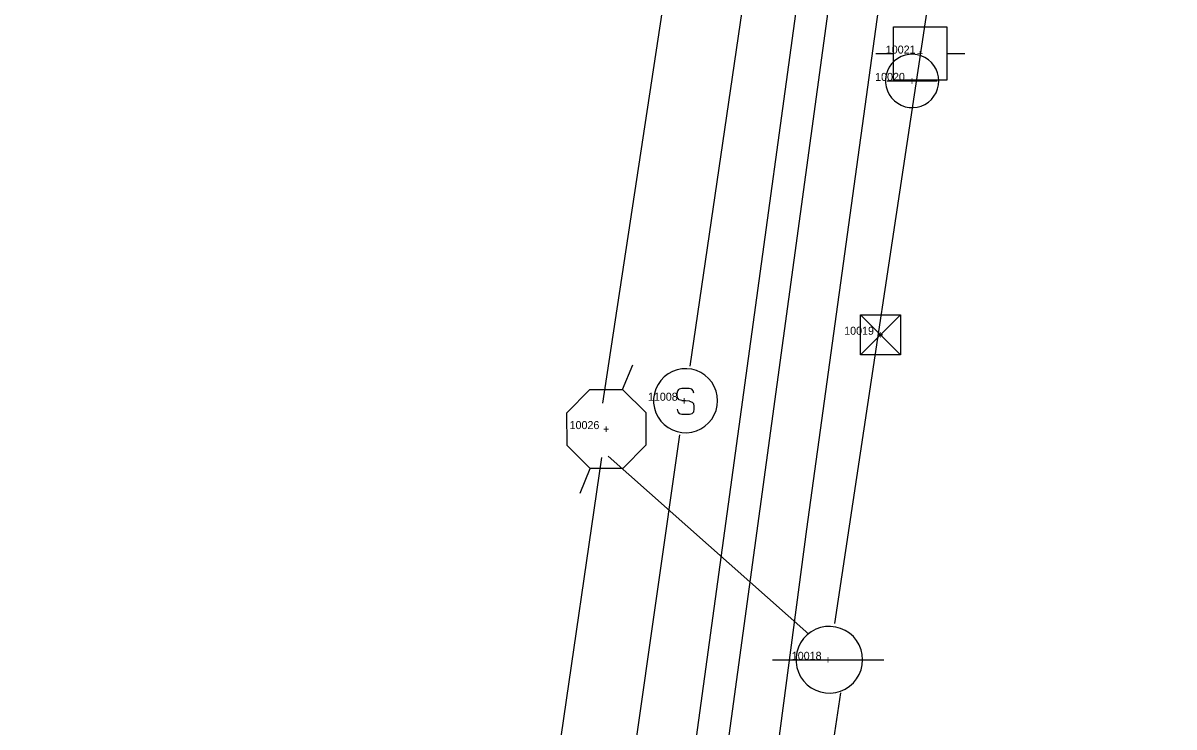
# Model space of a CAD drawing. Extents: x 1795905 to 1799611, y 243768 to 252016.
# Drawn here: x 1797411.2 to 1797626.9, y 244846.2 to 244978 of the extents above; entities that cross this region are included whole.
import ezdxf

# ---------------------------------------------------------------- set-up
doc = ezdxf.new("R2010")
doc.units = 0
for name, color, linetype in [('Level 50', 7, 'Continuous'), ('LS-SURVEY POINT', 7, 'Continuous'), ('OHUT', 7, 'Continuous'), ('OHUTTXT', 7, 'Continuous'), ('UGUT', 7, 'Continuous'), ('UGUTTXT', 7, 'Continuous')]:
    doc.layers.add(name, color=color, linetype=linetype)

msp = doc.modelspace()

# ---------------------------------------------------------------- linework, layer by layer
at = {"layer": 'Level 50'}
for p, q in [((1797523.61, 244909.35), (1797525.51, 244913.98)), ((1797515.63, 244889.93), (1797517.53, 244894.55))]:
    msp.add_line(p, q, dxfattribs=at)
msp.add_lwpolyline([(1797523.65, 244894.57), (1797517.53, 244894.55), (1797513.19, 244898.87), (1797513.17, 244904.99), (1797517.49, 244909.34), (1797523.61, 244909.35), (1797527.95, 244905.03), (1797527.97, 244898.91)], close=True, dxfattribs=at)
at = {"layer": 'OHUT'}
for p, q in [((1797574.38, 244977.28), (1797584.38, 244977.28)), ((1797574.38, 244967.28), (1797574.38, 244977.28)), ((1797584.38, 244977.28), (1797584.38, 244967.28)), ((1797571.05, 244972.28), (1797574.38, 244972.28)), ((1797584.38, 244972.28), (1797587.71, 244972.28)), ((1797584.38, 244967.28), (1797574.38, 244967.28)), ((1797551.72, 244858.74), (1797572.55, 244858.74))]:
    msp.add_line(p, q, dxfattribs=at)
msp.add_lwpolyline([(1797568.59, 244858.74), (1797568.52, 244859.7), (1797568.3, 244860.63), (1797567.95, 244861.52), (1797567.46, 244862.34), (1797566.85, 244863.08), (1797566.14, 244863.71), (1797565.33, 244864.24), (1797564.46, 244864.63), (1797563.54, 244864.88), (1797562.58, 244864.99), (1797561.63, 244864.95), (1797560.69, 244864.77), (1797559.79, 244864.45), (1797558.95, 244863.99), (1797558.19, 244863.41), (1797557.52, 244862.72), (1797556.97, 244861.94), (1797556.55, 244861.08), (1797556.26, 244860.17), (1797556.11, 244859.22), (1797556.11, 244858.27), (1797556.26, 244857.32), (1797556.55, 244856.41), (1797556.97, 244855.55), (1797557.52, 244854.77), (1797558.19, 244854.08), (1797558.95, 244853.5), (1797559.79, 244853.04), (1797560.69, 244852.72), (1797561.63, 244852.54), (1797562.58, 244852.5), (1797563.54, 244852.61), (1797564.46, 244852.86), (1797565.33, 244853.25), (1797566.14, 244853.77), (1797566.85, 244854.41), (1797567.46, 244855.15), (1797567.95, 244855.97), (1797568.3, 244856.86), (1797568.52, 244857.79)], close=True, dxfattribs=at)
at = {"layer": 'OHUTTXT'}
for p, q in [((1797563.38, 244865.55), (1797623.41, 245263.36)), ((1797519.91, 244906.82), (1797537.24, 245021.05)), ((1797505.88, 244801.76), (1797519.74, 244896.6)), ((1797520.91, 244896.85), (1797558.53, 244863.55)), ((1797542.26, 244706.1), (1797564.52, 244852.58))]:
    msp.add_line(p, q, dxfattribs=at)
at = {"layer": 'UGUT'}
for p, q in [((1797573.21, 244967.17), (1797582.54, 244967.17)), ((1797568.21, 244923.37), (1797575.71, 244915.87)), ((1797575.71, 244923.37), (1797568.21, 244915.87)), ((1797533.81, 244908.22), (1797533.81, 244908.67)), ((1797533.94, 244907.77), (1797533.81, 244908.22)), ((1797536.56, 244909.43), (1797536.05, 244909.56)), ((1797536.82, 244909.11), (1797536.56, 244909.43)), ((1797536.95, 244908.67), (1797536.82, 244909.11)), ((1797534.2, 244907.45), (1797533.94, 244907.77)), ((1797534.71, 244907.32), (1797534.2, 244907.45)), ((1797536.12, 244907.19), (1797534.71, 244907.32)), ((1797536.12, 244907.19), (1797536.63, 244907)), ((1797536.95, 244906.68), (1797536.63, 244907)), ((1797537.01, 244906.23), (1797536.95, 244906.68)), ((1797537.01, 244905.66), (1797537.01, 244906.23)), ((1797533.81, 244905.66), (1797533.94, 244905.21)), ((1797533.94, 244905.21), (1797534.2, 244904.89)), ((1797534.2, 244904.89), (1797534.71, 244904.76)), ((1797534.71, 244904.76), (1797536.12, 244904.76)), ((1797536.12, 244904.76), (1797536.63, 244904.89)), ((1797536.63, 244904.89), (1797536.95, 244905.21)), ((1797536.95, 244905.21), (1797537.01, 244905.66))]:
    msp.add_line(p, q, dxfattribs=at)
for points in [[(1797582.87, 244967.17), (1797582.82, 244967.93), (1797582.64, 244968.67), (1797582.36, 244969.38), (1797581.96, 244970.04), (1797581.48, 244970.63), (1797580.91, 244971.14), (1797580.26, 244971.56), (1797579.56, 244971.87), (1797578.83, 244972.07), (1797578.07, 244972.16), (1797577.3, 244972.13), (1797576.55, 244971.99), (1797575.83, 244971.73), (1797575.16, 244971.36), (1797574.55, 244970.9), (1797574.02, 244970.35), (1797573.58, 244969.72), (1797573.24, 244969.03), (1797573.01, 244968.3), (1797572.89, 244967.55), (1797572.89, 244966.78), (1797573.01, 244966.03), (1797573.24, 244965.3), (1797573.58, 244964.61), (1797574.02, 244963.98), (1797574.55, 244963.43), (1797575.16, 244962.97), (1797575.83, 244962.6), (1797576.55, 244962.34), (1797577.3, 244962.2), (1797578.07, 244962.17), (1797578.83, 244962.26), (1797579.56, 244962.46), (1797580.26, 244962.77), (1797580.91, 244963.19), (1797581.48, 244963.7), (1797581.96, 244964.29), (1797582.36, 244964.95), (1797582.64, 244965.66), (1797582.82, 244966.4)], [(1797568.21, 244923.37), (1797575.71, 244923.37), (1797575.71, 244915.87), (1797568.21, 244915.87)], [(1797541.4, 244907.26), (1797541.33, 244908.17), (1797541.12, 244909.07), (1797540.78, 244909.92), (1797540.31, 244910.71), (1797539.73, 244911.42), (1797539.04, 244912.03), (1797538.27, 244912.53), (1797537.43, 244912.9), (1797536.55, 244913.15), (1797535.63, 244913.25), (1797534.72, 244913.22), (1797533.81, 244913.04), (1797532.95, 244912.73), (1797532.14, 244912.29), (1797531.41, 244911.74), (1797530.78, 244911.07), (1797530.25, 244910.32), (1797529.84, 244909.5), (1797529.56, 244908.62), (1797529.42, 244907.71), (1797529.42, 244906.8), (1797529.56, 244905.89), (1797529.84, 244905.01), (1797530.25, 244904.19), (1797530.78, 244903.44), (1797531.41, 244902.78), (1797532.14, 244902.22), (1797532.95, 244901.78), (1797533.81, 244901.47), (1797534.72, 244901.3), (1797535.63, 244901.26), (1797536.55, 244901.37), (1797537.43, 244901.61), (1797538.27, 244901.99), (1797539.04, 244902.48), (1797539.73, 244903.1), (1797540.31, 244903.8), (1797540.78, 244904.59), (1797541.12, 244905.45), (1797541.33, 244906.34)]]:
    msp.add_lwpolyline(points, close=True, dxfattribs=at)
for points in [[(1797533.81, 244908.67), (1797533.94, 244909.11), (1797534.2, 244909.43)], [(1797536.05, 244909.56), (1797534.71, 244909.56), (1797534.2, 244909.43)]]:
    msp.add_lwpolyline(points, dxfattribs=at)
at = {"layer": 'UGUTTXT'}
for p, q in [((1797536.28, 244913.71), (1797595.07, 245314.82)), ((1797473.84, 244476.69), (1797534.35, 244900.9))]:
    msp.add_line(p, q, dxfattribs=at)
for points in [[(1797570.29, 244971.44), (1797619.21, 245325.58), (1797655.86, 245552.86)], [(1797528.99, 244782.88), (1797605.53, 245339.83), (1797411.24, 245347.9)], [(1797609.06, 245323.62), (1797536.58, 244793.88)], [(1797530.89, 244677.28), (1797558.11, 244883.23), (1797570.29, 244971.44)]]:
    msp.add_lwpolyline(points, dxfattribs=at)

# ---------------------------------------------------------------- texts
at = {"layer": 'LS-SURVEY POINT'}
for s, p in [('10021', (1797572.93, 244972.28)), ('+', (1797578.75, 244971.53)), ('10020', (1797570.93, 244967.17)), ('+', (1797577.25, 244966.42)), ('10019', (1797565.13, 244919.62)), ('+', (1797571.33, 244918.87)), ('11008', (1797528.35, 244907.26)), ('+', (1797534.55, 244906.51)), ('10026', (1797513.67, 244901.95)), ('+', (1797519.94, 244901.2)), ('10018', (1797555.31, 244858.74)), ('+', (1797561.51, 244857.99))]:
    msp.add_text(s, height=1.5, dxfattribs=at).set_placement(p)
at = {"layer": 'UGUT'}
msp.add_text('+', height=1, rotation=360, dxfattribs=at).set_placement((1797571.53, 244919.12))

doc.saveas('drawing.dxf')
